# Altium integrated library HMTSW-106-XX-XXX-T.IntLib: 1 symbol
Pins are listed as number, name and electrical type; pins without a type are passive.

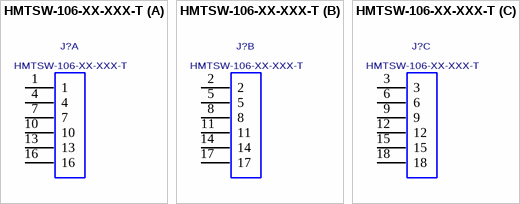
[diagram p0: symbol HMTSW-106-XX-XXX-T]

## HMTSW-106-XX-XXX-T
designator J?
.025[0.64] SQ. POST TERMINAL STRIP ASSEMBLY.; MANUFACTURER: SAMTEC
footprint HMTSW-106-XX-XXX-T
part A pins: 1, 4, 7, 10, 13, 16
part B pins: 2, 5, 8, 11, 14, 17
part C pins: 3, 6, 9, 12, 15, 18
